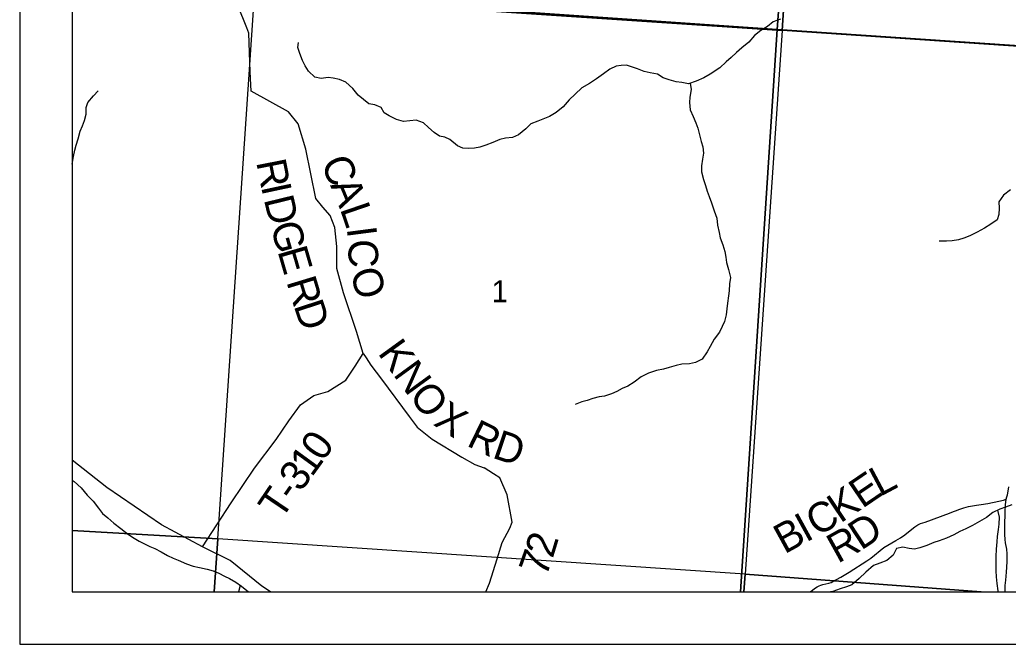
# Model space of a CAD drawing. Extents: x 39.8 to 73.8, y 13 to 35.
# Drawn here: x 41.763 to 43.656, y 26.965 to 28.16 of the extents above; entities that cross this region are included whole.
import ezdxf

# ---------------------------------------------------------------- set-up
doc = ezdxf.new("R2010")
doc.units = 0
for name, color, linetype in [('GM_X_Corporation', 7, 'Continuous'), ('GM_X_County_Road', 7, 'Continuous'), ('GM_X_Minor_River', 7, 'Continuous'), ('GM_X_Section_Text', 7, 'Continuous'), ('GM_X_Township_Road', 7, 'Continuous'), ('GM_X_Township_Road_Text', 7, 'Continuous'), ('SH_Data', 7, 'Continuous')]:
    doc.layers.add(name, color=color, linetype=linetype)

msp = doc.modelspace()

# ---------------------------------------------------------------- linework, layer by layer
at = {"layer": 'GM_X_Corporation'}
for points in [[(41.863, 33.865), (41.863, 28.2309), (42.171, 28.21), (42.2033, 28.2078), (42.215, 28.2104), (42.6574, 28.1799), (43.2131, 28.1416), (43.2721, 28.9438), (43.2726, 28.9503), (43.3304, 29.7365)], [(43.3304, 29.7365), (43.2726, 28.9503), (43.2721, 28.9438), (43.2131, 28.1416), (43.9992, 28.0883), (44.127, 28.0796), (44.1422, 28.0786), (45.3064, 27.9996), (46.1767, 27.9406), (46.6011, 27.9118), (46.7316, 27.9029), (46.7775, 27.8998), (46.7905, 27.899), (47.095, 27.8783), (47.5149, 27.8498)]]:
    msp.add_lwpolyline(points, dxfattribs=at)
for points in [[(42.2872, 29.2147), (43.2893, 29.1598), (43.2226, 28.1399), (42.2243, 28.2066)], [(43.2893, 29.1598), (44.3, 29.0715), (44.237, 28.0712), (44.2308, 28.0712), (43.2226, 28.1399)], [(41.863, 28.2309), (41.863, 27.065), (43.1433, 27.065), (43.2131, 28.1416), (42.6574, 28.1799), (42.215, 28.2104), (42.2033, 28.2078), (42.171, 28.21)], [(41.863, 28.2307), (41.863, 27.1824), (42.1421, 27.167), (42.2122, 28.2073)], [(42.2122, 28.2073), (42.2243, 28.2066), (43.2226, 28.1399), (43.1518, 27.0988), (42.1421, 27.167)], [(43.1433, 27.065), (48.663, 27.065), (48.663, 27.7809), (47.5414, 27.8484), (47.5149, 27.8498), (47.095, 27.8783), (46.7905, 27.899), (46.7775, 27.8998), (46.7316, 27.9029), (46.6011, 27.9118), (46.1767, 27.9406), (45.3064, 27.9996), (44.1422, 28.0786), (44.127, 28.0796), (43.9992, 28.0883), (43.2131, 28.1416)], [(43.6037, 27.065), (44.1682, 27.065), (44.2308, 28.0712), (43.2226, 28.1399), (43.1518, 27.0988)], [(41.863, 27.1824), (41.863, 27.065), (42.1354, 27.065), (42.1421, 27.167)], [(42.1354, 27.065), (43.1495, 27.065), (43.1518, 27.0988), (42.1421, 27.167)], [(43.1495, 27.065), (43.6037, 27.065), (43.1518, 27.0988)]]:
    msp.add_lwpolyline(points, close=True, dxfattribs=at)
at = {"layer": 'GM_X_County_Road'}
for points in [[(42.2429, 27.065), (42.2265, 27.0764), (42.166, 27.1255), (42.1129, 27.1515), (42.0344, 27.1937), (41.9299, 27.2651), (41.863, 27.3171)], [(43.6501, 27.065), (43.65, 27.0665), (43.6502, 27.0771), (43.6512, 27.0878), (43.6523, 27.1027), (43.6536, 27.1225), (43.6539, 27.1316), (43.6538, 27.1378), (43.653, 27.147), (43.6508, 27.1592), (43.65, 27.1654), (43.6493, 27.1748), (43.6491, 27.1903), (43.6496, 27.2193), (43.6503, 27.2319), (43.6516, 27.2426), (43.6533, 27.2473), (43.6543, 27.251), (43.6549, 27.2544), (43.6567, 27.2663)]]:
    msp.add_lwpolyline(points, dxfattribs=at)
at = {"layer": 'GM_X_Minor_River'}
for p, q in [((43.047, 28.0389), (43.0484, 28.0265)), ((41.8934, 28.002), (41.9043, 28.0145)), ((41.9043, 28.0145), (41.913, 28.0244)), ((43.0484, 28.0265), (43.0462, 28.0121)), ((41.8904, 27.9921), (41.8934, 28.002)), ((43.0462, 28.0121), (43.0454, 28.0018)), ((43.0454, 28.0018), (43.047, 27.9878)), ((41.8867, 27.9671), (41.8901, 27.9796)), ((41.8901, 27.9796), (41.8904, 27.9921)), ((43.047, 27.9878), (43.0524, 27.9749)), ((41.8784, 27.9469), (41.8833, 27.9572)), ((41.8833, 27.9572), (41.8867, 27.9671)), ((43.0524, 27.9749), (43.0573, 27.9632)), ((43.0573, 27.9632), (43.0611, 27.9526)), ((41.8747, 27.9325), (41.8784, 27.9469)), ((43.0611, 27.9526), (43.0646, 27.9398)), ((43.0646, 27.9398), (43.068, 27.9273)), ((41.8687, 27.9105), (41.871, 27.9204)), ((41.871, 27.9204), (41.8747, 27.9325)), ((43.068, 27.9273), (43.0711, 27.9167)), ((41.8661, 27.8984), (41.8687, 27.9105)), ((43.0723, 27.9049), (43.0704, 27.8932)), ((43.0711, 27.9167), (43.0723, 27.9049)), ((41.863, 27.884), (41.8639, 27.8877)), ((41.8639, 27.8877), (41.8661, 27.8984)), ((43.0704, 27.8932), (43.0682, 27.8803)), ((43.0682, 27.8803), (43.0686, 27.8689)), ((43.0686, 27.8689), (43.0725, 27.8545)), ((43.0725, 27.8545), (43.0759, 27.8432)), ((43.0759, 27.8432), (43.0794, 27.8322)), ((43.0794, 27.8322), (43.0832, 27.822)), ((43.6467, 27.8245), (43.6377, 27.8116)), ((43.6599, 27.8348), (43.6467, 27.8245)), ((43.0832, 27.822), (43.0878, 27.8099)), ((43.0878, 27.8099), (43.0924, 27.7947)), ((43.6377, 27.8116), (43.6381, 27.7994)), ((43.0924, 27.7947), (43.0977, 27.7803)), ((43.6378, 27.7873), (43.6344, 27.7771)), ((43.6381, 27.7994), (43.6378, 27.7873)), ((43.0977, 27.7803), (43.0993, 27.7671)), ((43.6223, 27.7687), (43.6102, 27.761)), ((43.6344, 27.7771), (43.6223, 27.7687)), ((43.0993, 27.7671), (43.102, 27.7531)), ((43.102, 27.7531), (43.1043, 27.7425)), ((43.5966, 27.7534), (43.5823, 27.7469)), ((43.6102, 27.761), (43.5966, 27.7534)), ((43.1043, 27.7425), (43.1092, 27.7292)), ((43.5376, 27.7365), (43.5233, 27.7364)), ((43.5482, 27.7369), (43.5376, 27.7365)), ((43.5607, 27.7388), (43.5482, 27.7369)), ((43.5709, 27.7423), (43.5607, 27.7388)), ((43.5823, 27.7469), (43.5709, 27.7423)), ((43.1092, 27.7292), (43.1131, 27.7164)), ((43.1131, 27.7164), (43.115, 27.7058)), ((43.115, 27.7058), (43.1162, 27.6955)), ((43.1162, 27.6955), (43.12, 27.6819)), ((43.12, 27.6819), (43.1238, 27.6668)), ((43.122, 27.6546), (43.1213, 27.6414)), ((43.1238, 27.6668), (43.122, 27.6546)), ((43.1213, 27.6414), (43.1202, 27.6315)), ((43.1183, 27.6178), (43.1172, 27.6072)), ((43.1202, 27.6315), (43.1183, 27.6178)), ((43.1172, 27.6072), (43.1154, 27.5955)), ((43.1124, 27.5829), (43.1079, 27.5731)), ((43.1154, 27.5955), (43.1124, 27.5829)), ((43.103, 27.5624), (43.0925, 27.5491)), ((43.1079, 27.5731), (43.103, 27.5624)), ((43.0925, 27.5491), (43.0849, 27.5351)), ((43.0793, 27.5244), (43.0699, 27.5107)), ((43.0849, 27.5351), (43.0793, 27.5244)), ((43.0567, 27.5039), (43.0453, 27.5019)), ((43.0699, 27.5107), (43.0567, 27.5039)), ((42.967, 27.4838), (42.9527, 27.4765)), ((42.9822, 27.4888), (42.967, 27.4838)), ((42.9954, 27.4915), (42.9822, 27.4888)), ((43.0064, 27.4945), (42.9954, 27.4915)), ((43.02, 27.4984), (43.0064, 27.4945)), ((43.0306, 27.5007), (43.02, 27.4984)), ((43.0453, 27.5019), (43.0306, 27.5007)), ((42.9395, 27.4666), (42.9274, 27.4589)), ((42.9527, 27.4765), (42.9395, 27.4666)), ((42.9062, 27.449), (42.896, 27.444)), ((42.9168, 27.4544), (42.9062, 27.449)), ((42.9274, 27.4589), (42.9168, 27.4544)), ((42.8393, 27.4286), (42.8268, 27.4236)), ((42.8495, 27.4317), (42.8393, 27.4286)), ((42.8601, 27.4351), (42.8495, 27.4317)), ((42.8726, 27.4382), (42.8601, 27.4351)), ((42.8824, 27.4398), (42.8726, 27.4382)), ((42.896, 27.444), (42.8824, 27.4398)), ((43.6352, 27.2215), (43.6383, 27.2082)), ((43.6383, 27.2082), (43.6379, 27.1946)), ((43.6365, 27.1847), (43.6346, 27.171)), ((43.6379, 27.1946), (43.6365, 27.1847)), ((43.6346, 27.171), (43.6339, 27.1608)), ((43.6328, 27.1472), (43.6321, 27.1331)), ((43.6339, 27.1608), (43.6328, 27.1472)), ((43.6321, 27.1331), (43.6318, 27.1187)), ((43.6318, 27.1187), (43.6322, 27.1055)), ((43.6322, 27.1055), (43.6326, 27.0941)), ((43.6326, 27.0941), (43.6338, 27.0812)), ((42.1853, 27.0776), (42.1817, 27.065)), ((43.6338, 27.0812), (43.6357, 27.0672)), ((43.6357, 27.0672), (43.636, 27.065))]:
    msp.add_line(p, q, dxfattribs=at)
for points in [[(43.2194, 28.1614), (43.2058, 28.156), (43.1948, 28.1476), (43.182, 28.1396), (43.1699, 28.1301), (43.159, 28.1175), (43.1458, 28.1065), (43.1352, 28.0977), (43.1254, 28.0878), (43.1156, 28.0794), (43.1035, 28.0684), (43.085, 28.0558), (43.0729, 28.0493), (43.0582, 28.0428), (43.0438, 28.0378), (43.0306, 28.04), (43.0196, 28.0411), (43.0067, 28.0449), (42.9953, 28.049), (42.9839, 28.0561), (42.9703, 28.0587), (42.9586, 28.0613), (42.9457, 28.0662), (42.9343, 28.0703), (42.9245, 28.0733), (42.9146, 28.0729), (42.9048, 28.0713), (42.8927, 28.0656), (42.8806, 28.0568), (42.8674, 28.0473), (42.8538, 28.0385), (42.8395, 28.0297), (42.8263, 28.0179), (42.8153, 28.0069), (42.8036, 27.9935), (42.79, 27.9829), (42.7772, 27.9748), (42.7553, 27.9664), (42.7413, 27.961), (42.7323, 27.9515), (42.7183, 27.9401), (42.7066, 27.9351), (42.6933, 27.9335), (42.682, 27.9312), (42.6691, 27.9251), (42.6552, 27.9201), (42.6438, 27.9163), (42.6336, 27.9147), (42.6226, 27.9135), (42.6113, 27.9142), (42.601, 27.9191), (42.5862, 27.9308), (42.5768, 27.9353), (42.5669, 27.9375), (42.5563, 27.9443), (42.5457, 27.9537), (42.5362, 27.9632), (42.5218, 27.968), (42.51, 27.9668), (42.4979, 27.9653), (42.4843, 27.9694), (42.4706, 27.9765)], [(42.4706, 27.9765), (42.4608, 27.9818), (42.4547, 27.992), (42.4429, 27.9972), (42.4312, 27.9991), (42.421, 28.0074), (42.4111, 28.016), (42.4008, 28.0285), (42.3875, 28.0409), (42.375, 28.0458), (42.3633, 28.0484), (42.3534, 28.0499), (42.3402, 28.0479), (42.3281, 28.0501), (42.3159, 28.0618), (42.3098, 28.0717), (42.3045, 28.0823), (42.2992, 28.0955), (42.2953, 28.1072), (42.2964, 28.1167)], [(41.863, 27.2789), (41.8672, 27.2764), (41.8805, 27.264), (41.8922, 27.2504), (41.9033, 27.2387), (41.9135, 27.2251), (41.9215, 27.2153), (41.9314, 27.2066), (41.9431, 27.1968), (41.9568, 27.1863), (41.9712, 27.1753), (41.9818, 27.1678), (41.9917, 27.1625), (42.0016, 27.1569), (42.0118, 27.152), (42.0213, 27.1479), (42.0338, 27.1419), (42.0459, 27.1347), (42.0565, 27.1295), (42.0664, 27.1257), (42.0823, 27.1186), (42.0948, 27.1141), (42.1069, 27.1119), (42.1217, 27.1089), (42.1335, 27.1052), (42.1444, 27.1011), (42.1551, 27.0954), (42.1645, 27.0909), (42.1767, 27.0838), (42.1877, 27.0759), (42.2009, 27.065)], [(43.6624, 27.2318), (43.6507, 27.2276), (43.6397, 27.2237), (43.6265, 27.2172), (43.6141, 27.2077), (43.6008, 27.1997), (43.5872, 27.1921), (43.5744, 27.1856), (43.5631, 27.1806), (43.5513, 27.1745), (43.5374, 27.168), (43.5238, 27.163), (43.5132, 27.1595), (43.5, 27.1538), (43.4867, 27.1492), (43.4765, 27.1468), (43.4663, 27.1483), (43.4538, 27.1509), (43.4417, 27.1482), (43.4353, 27.1353), (43.4236, 27.125), (43.4096, 27.12), (43.3975, 27.1154), (43.3832, 27.1032), (43.3704, 27.091), (43.3564, 27.0788), (43.3458, 27.075), (43.3337, 27.0708), (43.3201, 27.0662), (43.3153, 27.065)]]:
    msp.add_lwpolyline(points, dxfattribs=at)
at = {"layer": 'GM_X_Township_Road'}
for points in [[(42.1976, 28.1445), (42.1805, 28.1874)], [(42.4208, 27.5215), (42.4077, 27.5637), (42.3826, 27.6373), (42.3701, 27.6843), (42.3704, 27.726), (42.3666, 27.7625), (42.3571, 27.7856), (42.3431, 27.8015), (42.3298, 27.8182), (42.3108, 27.9127), (42.2963, 27.9608), (42.2773, 27.9839), (42.206, 28.0233), (42.2044, 28.0605), (42.2016, 28.1345), (42.1976, 28.1445)], [(42.1129, 27.1515), (42.1679, 27.2354), (42.2127, 27.3019), (42.2537, 27.357), (42.2779, 27.3923), (42.3007, 27.4232), (42.3263, 27.4413), (42.3529, 27.449), (42.3875, 27.4703), (42.405, 27.4972), (42.4208, 27.5215), (42.4265, 27.513)], [(42.4265, 27.513), (42.4355, 27.4993), (42.4554, 27.4722), (42.5085, 27.4006), (42.5241, 27.3807), (42.5526, 27.3577), (42.6094, 27.3233), (42.6346, 27.3087), (42.6525, 27.3026)], [(42.6554, 27.065), (42.6625, 27.0817), (42.6773, 27.1284), (42.6864, 27.1596), (42.7016, 27.1873), (42.7057, 27.1983), (42.6966, 27.251), (42.6823, 27.2833), (42.6704, 27.2911), (42.6525, 27.3026)], [(43.2768, 27.065), (43.2809, 27.0686), (43.2851, 27.0719), (43.2896, 27.0747), (43.2937, 27.0766), (43.2972, 27.0779), (43.3005, 27.079), (43.3066, 27.0805), (43.3123, 27.0817), (43.3168, 27.0833), (43.3198, 27.0849), (43.3351, 27.0933), (43.3513, 27.103), (43.3851, 27.1248), (43.3927, 27.13), (43.3999, 27.1355), (43.4104, 27.1446), (43.4175, 27.1498), (43.4254, 27.1546), (43.4403, 27.1636), (43.4495, 27.1686), (43.4579, 27.1745), (43.4681, 27.1824), (43.4769, 27.1894), (43.4824, 27.1932), (43.488, 27.196), (43.4966, 27.1989), (43.5433, 27.2159), (43.5507, 27.2188), (43.5548, 27.2203), (43.5631, 27.2236), (43.571, 27.2263), (43.58, 27.2285), (43.5952, 27.2314), (43.6039, 27.2324), (43.6165, 27.2343), (43.6375, 27.239), (43.6464, 27.2409), (43.6516, 27.2426)]]:
    msp.add_lwpolyline(points, dxfattribs=at)
at = {"layer": 'SH_Data'}
for p, q in [((41.763, 33.965), (41.763, 26.965)), ((41.863, 33.865), (41.863, 27.065)), ((41.863, 27.065), (48.663, 27.065)), ((41.863, 27.065), (41.863, 27.065)), ((41.763, 26.965), (48.763, 26.965))]:
    msp.add_line(p, q, dxfattribs=at)

# ---------------------------------------------------------------- texts
at = {"layer": 'GM_X_Section_Text'}
msp.add_text('1', height=0.0419, rotation=0, dxfattribs=at).set_placement((42.6665, 27.6196))
at = {"layer": 'GM_X_Township_Road_Text'}
for s, rotation, p in [('R', 281.2181, (42.2155, 27.888)), ('C', 292.7712, (42.3388, 27.8866)), ('I', 282.0259, (42.2248, 27.8413)), ('A', 292.6294, (42.3568, 27.8436)), ('D', 283.7249, (42.23, 27.8167)), ('L', 288.9256, (42.3757, 27.7984)), ('G', 285.7732, (42.2425, 27.766)), ('I', 277.4368, (42.3888, 27.7611)), ('C', 271.4755, (42.3917, 27.7395)), ('E', 286.1901, (42.2562, 27.7175)), ('O', 285.7139, (42.3952, 27.6777)), ('R', 286.9189, (42.2732, 27.6591)), ('D', 288.1467, (42.2871, 27.6132)), ('K', 305.9395, (42.4474, 27.5221)), ('N', 306.0321, (42.4768, 27.4815)), ('O', 307.058, (42.5069, 27.4402)), ('X', 327.2475, (42.553, 27.3855)), ('R', 334.154, (42.6166, 27.3458)), ('0', 55.0391, (42.3433, 27.3127)), ('D', 341.4359, (42.6659, 27.3225)), ('1', 53.9687, (42.322, 27.2834)), ('3', 53.0031, (42.3003, 27.2546)), ('E', 34.2134, (43.3762, 27.2237)), ('L', 28.018, (43.41, 27.2467)), ('T', 55.8369, (42.2633, 27.2011)), ('-', 54.5041, (42.287, 27.236)), ('K', 33.709, (43.3342, 27.1956)), ('C', 28.7988, (43.2887, 27.1704)), ('B', 28.765, (43.2273, 27.1367)), ('I', 28.765, (43.2683, 27.1591)), ('D', 33.3048, (43.374, 27.1437)), ('R', 29.0269, (43.3293, 27.1187)), ('2', 72.9983, (42.7834, 27.1279)), ('7', 70.4882, (42.7708, 27.0923))]:
    msp.add_text(s, height=0.0568, rotation=rotation, dxfattribs=at).set_placement(p)

doc.saveas('drawing.dxf')
